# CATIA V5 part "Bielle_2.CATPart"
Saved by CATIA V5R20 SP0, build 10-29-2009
Part number: Bielle_2
Bounding box of the stored display mesh (mm): x 1 to 2, y 37.504 to 73.888, z 12.504 to 26.388
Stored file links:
  C:\Users\J\IAO_2012_jgossard\Bielle_2.CATPart
  C:\Users\J\IAO_2012_jgossard\jgossard.CATProduct
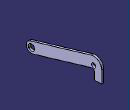
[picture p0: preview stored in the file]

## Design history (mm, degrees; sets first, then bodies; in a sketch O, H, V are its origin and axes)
Set1
  Plane1 "Plan_ref": linked copy from another document
  Point1 "Point_G": linked copy from another document
  Point2 "Point_F": linked copy from another document
Body1 (main body)
  Sketch1 on Plane1, origin (0, 0, 0), H (0, 1, 0), V (0, 0, 1)
    line L1 (40.7146, 12.6043) -> (69.1026, 21.0724)
    line L2 (39.2854, 17.3957) -> (68.8885, 26.2262)
    arc A1 centre (40, 15) radius 2.5 from (39.2854, 17.3957) to (40.7146, 12.6043) ccw
    point P5 (40, 15)
    line L3 (73.8885, 22.5) -> (73.8885, 16.6195)
    point P6 (73.8885, 22.5)
    line L4 (70.3885, 20.1141) -> (70.3885, 16.6195)
    arc A2 centre (70, 22.5) radius 3.8885 from (68.8885, 26.2262) to (73.8885, 22.5) cw
    point P10 (70, 22.5)
    arc A3 centre (69.3885, 20.1141) radius 1 from (69.1026, 21.0724) to (70.3885, 20.1141) cw
    line L5 (70.3885, 16.6195) -> (73.8885, 16.6195)
    reference projected point E1 (40, 15) from Point1
    reference projected point E2 (70, 22.5) from Point2
    reference projected point E3 (70, 22.5) from Point2
    radius A1 = 2.5
    radius A3 = 1
    length L5 = 3.5
    distance L5 E3 = 5.8805
    tangency: L2 A1, L1 A1, A3 L1, L4 A3, L3 A2, A2 L2
    coincidence: P6 L1, P5 E1, P10 E2
    vertical: L3 V, L4 V
    parallelism: L1 L2
    perpendicularity: L5 L3
  Pad1: profile Sketch1, direction (1, 0, 0), length 2, opposite side length -1
  Sketch2 on start face of Pad1, origin (1, 40.9652, 6.1882), H (0, -1, 0), V (0, 0, 1)
    point P1 (0.9652, 8.8118)
    reference projected point E1 (0.9652, 8.8118) from Point1
    coincidence: P1 E1
  Hole1: placed by Sketch2, at (1, 40, 15) direction (1, 0, 0), diameter 3, through (limit type 6)
  Sketch3 on end face of Pad1, origin (2, 69.9374, 18.484), H (0, 1, 0), V (0, 0, 1)
    point P1 (0.0626, 4.016)
    reference projected point E1 (0.0626, 4.016) from Point2
    coincidence: P1 E1
  Hole2: placed by Sketch3, at (2, 70, 22.5) direction (-1, 0, 0), diameter 2, through (limit type 6)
